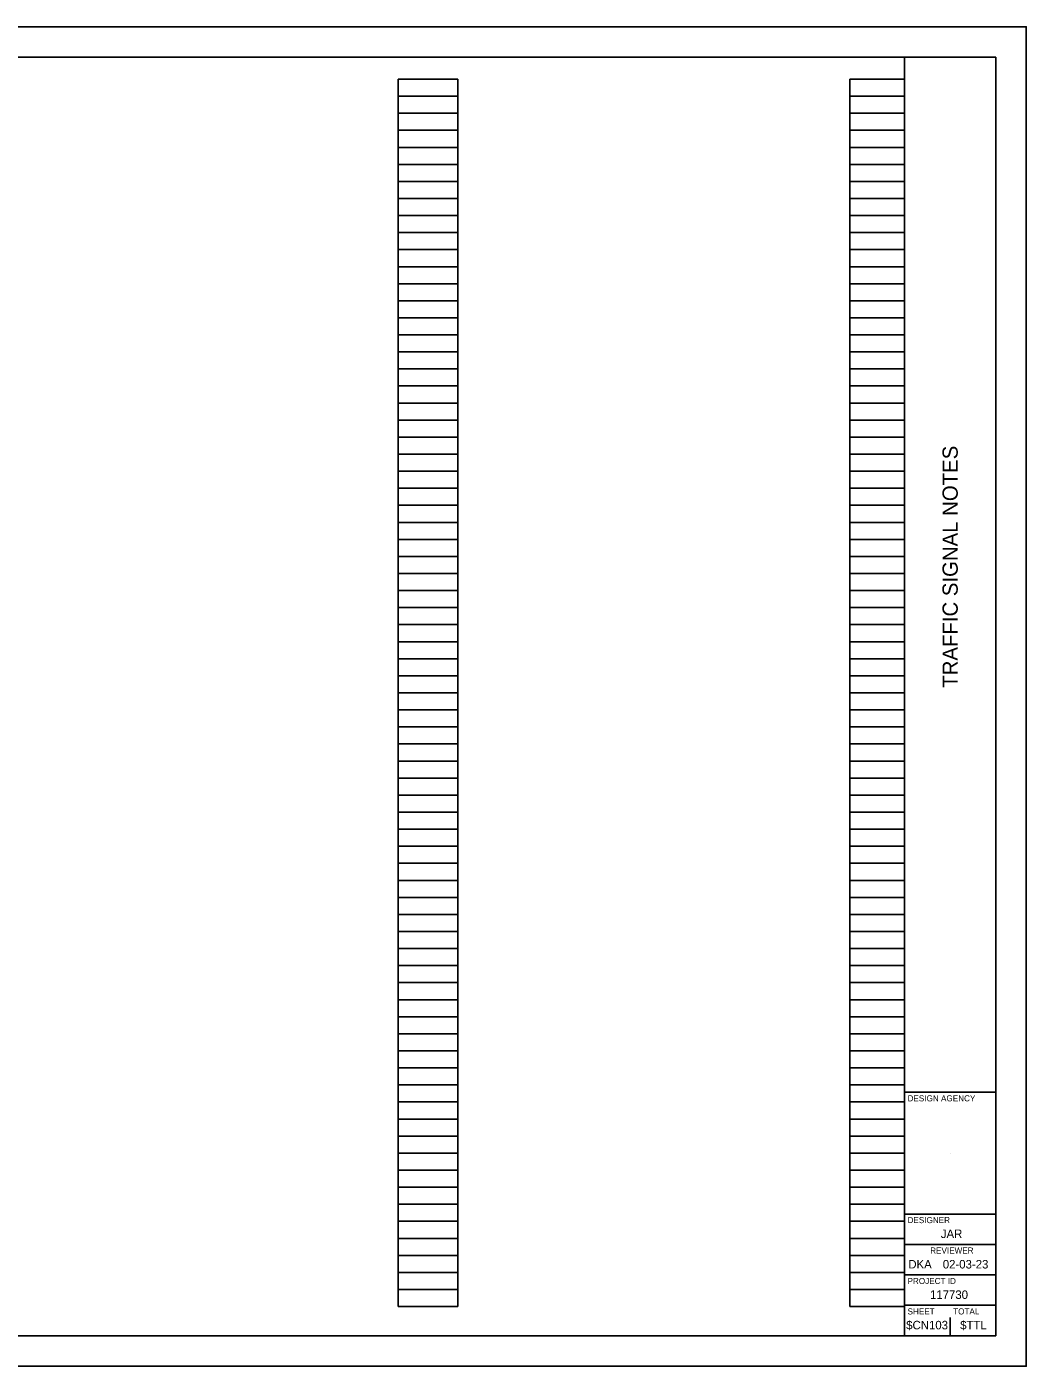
# Model space of a CAD drawing. Extents: x 0 to 34, y 0 to 22.
# Drawn here: x 17.58 to 34, y 0 to 22 of the extents above; entities that cross this region are included whole.
import ezdxf

# ---------------------------------------------------------------- set-up
doc = ezdxf.new("R2010")
doc.units = 0
for name, color, linetype in [('SH_Border', 7, 'Continuous'), ('SH_Cut_Line', 7, 'Continuous'), ('SH_Data', 7, 'Continuous')]:
    doc.layers.add(name, color=color, linetype=linetype)

msp = doc.modelspace()

# ---------------------------------------------------------------- linework, layer by layer
at = {"layer": 'SH_Border'}
for p, q in [((32, 0.5), (32, 21.5)), ((32, 4.5), (33.5, 4.5)), ((32, 2.5), (33.5, 2.5)), ((32, 2), (33.5, 2)), ((32, 1.5), (33.5, 1.5)), ((32, 1), (33.5, 1))]:
    msp.add_line(p, q, dxfattribs=at)
msp.add_lwpolyline([(1.5, 21.5), (33.5, 21.5), (33.5, 0.5), (1.5, 0.5)], close=True, dxfattribs=at)
at = {"layer": 'SH_Cut_Line'}
msp.add_lwpolyline([(0, 0), (34, 0), (34, 22), (0, 22)], close=True, dxfattribs=at)
at = {"layer": 'SH_Data'}
for p, q in [((23.68, 0.98), (23.68, 21.14)), ((23.68, 21.14), (24.66, 21.14)), ((24.66, 0.98), (24.66, 21.14)), ((31.1, 0.98), (31.1, 21.14)), ((31.1, 21.14), (32, 21.14)), ((32, 0.98), (32, 21.14)), ((23.68, 20.86), (24.66, 20.86)), ((31.1, 20.86), (32, 20.86)), ((23.68, 20.58), (24.66, 20.58)), ((31.1, 20.58), (32, 20.58)), ((23.68, 20.3), (24.66, 20.3)), ((31.1, 20.3), (32, 20.3)), ((23.68, 20.02), (24.66, 20.02)), ((31.1, 20.02), (32, 20.02)), ((23.68, 19.74), (24.66, 19.74)), ((31.1, 19.74), (32, 19.74)), ((23.68, 19.46), (24.66, 19.46)), ((31.1, 19.46), (32, 19.46)), ((23.68, 19.18), (24.66, 19.18)), ((31.1, 19.18), (32, 19.18)), ((23.68, 18.9), (24.66, 18.9)), ((31.1, 18.9), (32, 18.9)), ((23.68, 18.62), (24.66, 18.62)), ((31.1, 18.62), (32, 18.62)), ((23.68, 18.34), (24.66, 18.34)), ((31.1, 18.34), (32, 18.34)), ((23.68, 18.06), (24.66, 18.06)), ((31.1, 18.06), (32, 18.06)), ((23.68, 17.78), (24.66, 17.78)), ((31.1, 17.78), (32, 17.78)), ((23.68, 17.5), (24.66, 17.5)), ((31.1, 17.5), (32, 17.5)), ((23.68, 17.22), (24.66, 17.22)), ((31.1, 17.22), (32, 17.22)), ((23.68, 16.94), (24.66, 16.94)), ((31.1, 16.94), (32, 16.94)), ((23.68, 16.66), (24.66, 16.66)), ((31.1, 16.66), (32, 16.66)), ((23.68, 16.38), (24.66, 16.38)), ((31.1, 16.38), (32, 16.38)), ((23.68, 16.1), (24.66, 16.1)), ((31.1, 16.1), (32, 16.1)), ((23.68, 15.82), (24.66, 15.82)), ((31.1, 15.82), (32, 15.82)), ((23.68, 15.54), (24.66, 15.54)), ((31.1, 15.54), (32, 15.54)), ((23.68, 15.26), (24.66, 15.26)), ((31.1, 15.26), (32, 15.26)), ((23.68, 14.98), (24.66, 14.98)), ((31.1, 14.98), (32, 14.98)), ((23.68, 14.7), (24.66, 14.7)), ((31.1, 14.7), (32, 14.7)), ((23.68, 14.42), (24.66, 14.42)), ((31.1, 14.42), (32, 14.42)), ((23.68, 14.14), (24.66, 14.14)), ((31.1, 14.14), (32, 14.14)), ((23.68, 13.86), (24.66, 13.86)), ((31.1, 13.86), (32, 13.86)), ((23.68, 13.58), (24.66, 13.58)), ((31.1, 13.58), (32, 13.58)), ((23.68, 13.3), (24.66, 13.3)), ((31.1, 13.3), (32, 13.3)), ((23.68, 13.02), (24.66, 13.02)), ((31.1, 13.02), (32, 13.02)), ((23.68, 12.74), (24.66, 12.74)), ((31.1, 12.74), (32, 12.74)), ((23.68, 12.46), (24.66, 12.46)), ((31.1, 12.46), (32, 12.46)), ((23.68, 12.18), (24.66, 12.18)), ((31.1, 12.18), (32, 12.18)), ((23.68, 11.9), (24.66, 11.9)), ((31.1, 11.9), (32, 11.9)), ((23.68, 11.62), (24.66, 11.62)), ((31.1, 11.62), (32, 11.62)), ((23.68, 11.34), (24.66, 11.34)), ((31.1, 11.34), (32, 11.34)), ((23.68, 11.06), (24.66, 11.06)), ((31.1, 11.06), (32, 11.06)), ((23.68, 10.78), (24.66, 10.78)), ((31.1, 10.78), (32, 10.78)), ((23.68, 10.5), (24.66, 10.5)), ((31.1, 10.5), (32, 10.5)), ((23.68, 10.22), (24.66, 10.22)), ((31.1, 10.22), (32, 10.22)), ((23.68, 9.94), (24.66, 9.94)), ((31.1, 9.94), (32, 9.94)), ((23.68, 9.66), (24.66, 9.66)), ((31.1, 9.66), (32, 9.66)), ((23.68, 9.38), (24.66, 9.38)), ((31.1, 9.38), (32, 9.38)), ((23.68, 9.1), (24.66, 9.1)), ((31.1, 9.1), (32, 9.1)), ((23.68, 8.82), (24.66, 8.82)), ((31.1, 8.82), (32, 8.82)), ((23.68, 8.54), (24.66, 8.54)), ((31.1, 8.54), (32, 8.54)), ((23.68, 8.26), (24.66, 8.26)), ((31.1, 8.26), (32, 8.26)), ((23.68, 7.98), (24.66, 7.98)), ((31.1, 7.98), (32, 7.98)), ((23.68, 7.7), (24.66, 7.7)), ((31.1, 7.7), (32, 7.7)), ((23.68, 7.42), (24.66, 7.42)), ((31.1, 7.42), (32, 7.42)), ((23.68, 7.14), (24.66, 7.14)), ((31.1, 7.14), (32, 7.14)), ((23.68, 6.86), (24.66, 6.86)), ((31.1, 6.86), (32, 6.86)), ((23.68, 6.58), (24.66, 6.58)), ((31.1, 6.58), (32, 6.58)), ((23.68, 6.3), (24.66, 6.3)), ((31.1, 6.3), (32, 6.3)), ((23.68, 6.02), (24.66, 6.02)), ((31.1, 6.02), (32, 6.02)), ((23.68, 5.74), (24.66, 5.74)), ((31.1, 5.74), (32, 5.74)), ((23.68, 5.46), (24.66, 5.46)), ((31.1, 5.46), (32, 5.46)), ((23.68, 5.18), (24.66, 5.18)), ((31.1, 5.18), (32, 5.18)), ((23.68, 4.9), (24.66, 4.9)), ((31.1, 4.9), (32, 4.9)), ((23.68, 4.62), (24.66, 4.62)), ((31.1, 4.62), (32, 4.62)), ((23.68, 4.34), (24.66, 4.34)), ((31.1, 4.34), (32, 4.34)), ((23.68, 4.06), (24.66, 4.06)), ((31.1, 4.06), (32, 4.06)), ((23.68, 3.78), (24.66, 3.78)), ((31.1, 3.78), (32, 3.78)), ((23.68, 3.5), (24.66, 3.5)), ((31.1, 3.5), (32, 3.5)), ((32.75, 3.5), (32.75, 3.5)), ((23.68, 3.22), (24.66, 3.22)), ((31.1, 3.22), (32, 3.22)), ((23.68, 2.94), (24.66, 2.94)), ((31.1, 2.94), (32, 2.94)), ((23.68, 2.66), (24.66, 2.66)), ((31.1, 2.66), (32, 2.66)), ((23.68, 2.38), (24.66, 2.38)), ((31.1, 2.38), (32, 2.38)), ((23.68, 2.1), (24.66, 2.1)), ((31.1, 2.1), (32, 2.1)), ((23.68, 1.82), (24.66, 1.82)), ((31.1, 1.82), (32, 1.82)), ((23.68, 1.54), (24.66, 1.54)), ((31.1, 1.54), (32, 1.54)), ((23.68, 1.26), (24.66, 1.26)), ((31.1, 1.26), (32, 1.26)), ((23.68, 0.98), (24.66, 0.98)), ((31.1, 0.98), (32, 0.98)), ((32.375, 0.675), (32.375, 0.675)), ((32.75, 0.5), (32.75, 0.8))]:
    msp.add_line(p, q, dxfattribs=at)

# ---------------------------------------------------------------- texts
msp.add_text('TRAFFIC SIGNAL NOTES', height=0.25, rotation=90, dxfattribs=at).set_placement((32.875, 11.144))
for s, height, p in [('DESIGN AGENCY', 0.1, (32.05, 4.35)), ('DESIGNER', 0.1, (32.05, 2.35)), ('JAR', 0.14, (32.597, 2.105)), ('REVIEWER', 0.1, (32.422, 1.85)), ('DKA', 0.14, (32.063, 1.605)), ('02-03-23', 0.14, (32.629, 1.605)), ('PROJECT ID', 0.1, (32.05, 1.35)), ('117730', 0.14, (32.419, 1.105)), ('SHEET', 0.1, (32.05, 0.85)), ('TOTAL', 0.1, (32.8, 0.85)), ('$CN103', 0.14, (32.028, 0.605)), ('$TTL', 0.14, (32.915, 0.605))]:
    msp.add_text(s, height=height, dxfattribs=at).set_placement(p)

doc.saveas('drawing.dxf')
